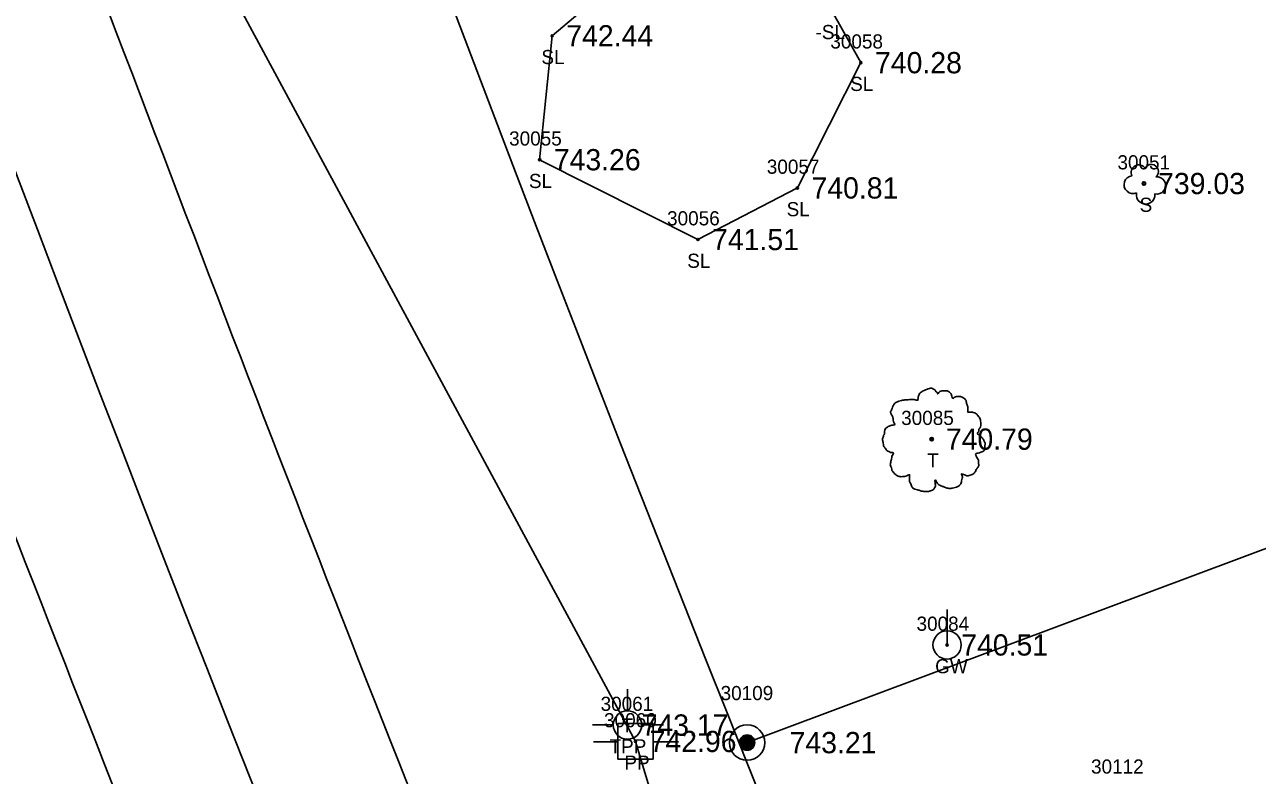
# Model space of a CAD drawing. Extents: x 1375131 to 1378678, y 999028 to 1004053.
# Drawn here: x 1376786.1 to 1376873.2, y 1002668.2 to 1002721.2 of the extents above; entities that cross this region are included whole.
import ezdxf

# ---------------------------------------------------------------- set-up
doc = ezdxf.new("R2010")
doc.units = 0
for name, color, linetype in [('RD_EX_Conc_txCode', 7, 'Continuous'), ('RD_EX_DV_Prop', 7, 'Continuous'), ('RD_EX_DV_Prop_txCode', 7, 'Continuous'), ('RD_EX_DV_PropPin', 7, 'Continuous'), ('RD_EX_Road', 7, 'Continuous'), ('RD_EX_RW', 7, 'Continuous'), ('RD_EX_SU_Elec', 7, 'Continuous'), ('RD_EX_TX_DV_Prop_ELEV', 7, 'Continuous'), ('RD_EX_TX_UT_ELEV', 7, 'Continuous'), ('RD_EX_TX_VEG_ELEV', 7, 'Continuous'), ('RD_EX_UT', 7, 'Continuous'), ('RD_EX_UT_txCode', 7, 'Continuous'), ('RD_EX_VEG', 7, 'Continuous'), ('RD_EX_VEG_txCode', 7, 'Continuous'), ('RD_HC_Cl', 7, 'Continuous'), ('RD_HC_Survey_ELEV', 7, 'Continuous'), ('RD_SMD_Locator', 7, 'Continuous')]:
    doc.layers.add(name, color=color, linetype=linetype)

msp = doc.modelspace()

# ---------------------------------------------------------------- linework, layer by layer
at = {"layer": 'RD_EX_DV_Prop'}
msp.add_line((1376836.626, 1002670.321), (1377239.883, 1002821.263), dxfattribs=at)
at = {"layer": 'RD_EX_DV_PropPin'}
for p, q in [((1376836.825, 1002670.055), (1376836.825, 1002670.961)), ((1376836.85, 1002670.039), (1376836.85, 1002670.977)), ((1376836.875, 1002670.026), (1376836.875, 1002670.99)), ((1376836.9, 1002670.013), (1376836.9, 1002671.003)), ((1376836.925, 1002670.003), (1376836.925, 1002671.013)), ((1376836.95, 1002669.994), (1376836.95, 1002671.022)), ((1376836.975, 1002669.986), (1376836.975, 1002671.03)), ((1376837, 1002669.979), (1376837, 1002671.037)), ((1376837.025, 1002669.974), (1376837.025, 1002671.042)), ((1376837.05, 1002669.97), (1376837.05, 1002671.046)), ((1376837.075, 1002669.967), (1376837.075, 1002671.049)), ((1376837.1, 1002669.965), (1376837.1, 1002671.051)), ((1376837.125, 1002669.965), (1376837.125, 1002671.051)), ((1376837.15, 1002669.965), (1376837.15, 1002671.051)), ((1376837.175, 1002669.967), (1376837.175, 1002671.049)), ((1376837.2, 1002669.97), (1376837.2, 1002671.046)), ((1376837.225, 1002669.974), (1376837.225, 1002671.042)), ((1376837.25, 1002669.979), (1376837.25, 1002671.037)), ((1376837.275, 1002669.986), (1376837.275, 1002671.03)), ((1376837.3, 1002669.994), (1376837.3, 1002671.022)), ((1376837.325, 1002670.003), (1376837.325, 1002671.013)), ((1376837.35, 1002670.013), (1376837.35, 1002671.003)), ((1376837.375, 1002670.026), (1376837.375, 1002670.99)), ((1376837.4, 1002670.039), (1376837.4, 1002670.977)), ((1376837.425, 1002670.055), (1376837.425, 1002670.961)), ((1376836.6, 1002670.368), (1376836.6, 1002670.648)), ((1376836.625, 1002670.295), (1376836.625, 1002670.721)), ((1376836.65, 1002670.244), (1376836.65, 1002670.772)), ((1376836.675, 1002670.203), (1376836.675, 1002670.813)), ((1376836.7, 1002670.169), (1376836.7, 1002670.847)), ((1376836.725, 1002670.14), (1376836.725, 1002670.876)), ((1376836.75, 1002670.115), (1376836.75, 1002670.901)), ((1376836.775, 1002670.092), (1376836.775, 1002670.924)), ((1376836.8, 1002670.073), (1376836.8, 1002670.943)), ((1376837.45, 1002670.073), (1376837.45, 1002670.943)), ((1376837.475, 1002670.092), (1376837.475, 1002670.924)), ((1376837.5, 1002670.115), (1376837.5, 1002670.901)), ((1376837.525, 1002670.14), (1376837.525, 1002670.876)), ((1376837.55, 1002670.169), (1376837.55, 1002670.847)), ((1376837.575, 1002670.203), (1376837.575, 1002670.813)), ((1376837.6, 1002670.244), (1376837.6, 1002670.772)), ((1376837.625, 1002670.295), (1376837.625, 1002670.721)), ((1376837.65, 1002670.368), (1376837.65, 1002670.648))]:
    msp.add_line(p, q, dxfattribs=at)
for radius in [1.25, 0.543]:
    msp.add_circle((1376837.125, 1002670.508), radius, dxfattribs=at)
at = {"layer": 'RD_EX_Road'}
for points in [[(1377013.314, 1002264.907), (1376982.808, 1002315.683), (1376952.468, 1002370.341), (1376923.174, 1002424.32), (1376895.644, 1002480.03), (1376870.11, 1002535.049), (1376846.329, 1002588.864), (1376822.292, 1002645.031), (1376786.564, 1002736.458)], [(1376994.747, 1002253.913), (1376964.909, 1002306.463), (1376934.396, 1002359.987), (1376904.773, 1002415.485), (1376877.271, 1002471.511), (1376851.037, 1002526.893), (1376827.48, 1002581.62), (1376804.191, 1002637.821), (1376768.457, 1002728.838)]]:
    msp.add_spline(points, degree=3, dxfattribs=at)
at = {"layer": 'RD_EX_RW'}
for radius in [2767, 2833]:
    msp.add_arc((1379404.86, 1003700.108), radius, 200.269954, 211.131166, dxfattribs=at)
at = {"layer": 'RD_EX_SU_Elec'}
for p, q in [((1376639.019, 1003023.14), (1376829.238, 1002670.592)), ((1376829.238, 1002670.592), (1376932.6, 1002329.066))]:
    msp.add_line(p, q, dxfattribs=at)
at = {"layer": 'RD_EX_UT'}
for p, q in [((1376851.25, 1002677.405), (1376851.25, 1002679.905)), ((1376828.672, 1002674.285), (1376828.672, 1002672.75)), ((1376830.483, 1002671.847), (1376827.983, 1002671.847)), ((1376827.983, 1002671.847), (1376827.983, 1002669.347)), ((1376830.483, 1002669.347), (1376830.483, 1002671.847)), ((1376826.207, 1002671.758), (1376827.672, 1002671.758)), ((1376829.672, 1002671.758), (1376831.207, 1002671.758)), ((1376826.268, 1002670.565), (1376828.002, 1002670.565)), ((1376830.448, 1002670.565), (1376832.268, 1002670.565)), ((1376827.983, 1002669.347), (1376830.483, 1002669.347))]:
    msp.add_line(p, q, dxfattribs=at)
for centre in [(1376851.25, 1002677.405), (1376828.672, 1002671.75)]:
    msp.add_circle(centre, 1, dxfattribs=at)
at = {"layer": 'RD_EX_VEG'}
msp.add_lwpolyline([(1376842.762, 1002723.226), (1376832.093, 1002727.803), (1376823.348, 1002720.418), (1376822.468, 1002711.668), (1376833.651, 1002706.033), (1376840.672, 1002709.675), (1376845.16, 1002718.521), (1376843.119, 1002722.182)], dxfattribs=at)
for centre, radius in [((1376865.158, 1002709.986), 0.125), ((1376850.164, 1002691.938), 0.125), ((1376850.158, 1002691.929), 0.00005)]:
    msp.add_circle(centre, radius, dxfattribs=at)
for centre, radius, start, end in [((1376864.797, 1002710.76), 0.542, 34.97629, 204.75602), ((1376865.681, 1002710.837), 0.497, 308.76261, 152.04674), ((1376864.376, 1002709.908), 0.628, 96.45179, 294.73401), ((1376866.078, 1002709.846), 0.609, 256.56668, 98.10463), ((1376865.281, 1002709.188), 0.659, 166.88266, 5.75893)]:
    msp.add_arc(centre, radius, start, end, dxfattribs=at)
for points in [[(1376850.23, 1002695.522), (1376850.08, 1002695.534), (1376849.918, 1002695.484), (1376849.793, 1002695.434), (1376849.68, 1002695.397), (1376849.568, 1002695.347), (1376849.418, 1002695.259), (1376849.305, 1002695.159), (1376849.243, 1002695.034), (1376849.218, 1002694.922), (1376849.193, 1002694.784), (1376849.193, 1002694.697), (1376849.13, 1002694.684), (1376849.055, 1002694.697), (1376848.931, 1002694.734), (1376848.806, 1002694.734), (1376848.681, 1002694.734), (1376848.506, 1002694.722), (1376848.331, 1002694.722), (1376848.193, 1002694.697), (1376848.031, 1002694.672), (1376847.844, 1002694.61), (1376847.669, 1002694.547), (1376847.519, 1002694.422), (1376847.394, 1002694.185), (1376847.331, 1002694.01), (1376847.256, 1002693.885), (1376847.331, 1002693.66), (1376847.419, 1002693.485), (1376847.431, 1002693.385), (1376847.469, 1002693.173), (1376847.519, 1002693.06), (1376847.581, 1002692.96), (1376847.544, 1002692.948), (1376847.356, 1002692.923), (1376847.206, 1002692.873), (1376846.994, 1002692.76), (1376846.881, 1002692.648), (1376846.831, 1002692.485), (1376846.819, 1002692.311), (1376846.769, 1002692.211), (1376846.732, 1002692.073), (1376846.719, 1002692.036), (1376846.694, 1002691.873), (1376846.744, 1002691.648), (1376846.757, 1002691.473), (1376846.819, 1002691.361), (1376846.894, 1002691.274), (1376846.981, 1002691.149), (1376847.181, 1002691.036), (1376847.344, 1002690.986), (1376847.444, 1002690.974), (1376847.356, 1002690.724), (1376847.331, 1002690.549), (1376847.269, 1002690.349), (1376847.269, 1002690.311), (1376847.244, 1002690.074), (1376847.319, 1002689.912), (1376847.356, 1002689.724), (1376847.444, 1002689.612), (1376847.581, 1002689.462), (1376847.744, 1002689.349), (1376847.993, 1002689.287), (1376848.193, 1002689.299), (1376848.481, 1002689.387), (1376848.606, 1002689.424), (1376848.593, 1002689.337), (1376848.606, 1002689.149), (1376848.606, 1002688.937), (1376848.681, 1002688.775), (1376848.731, 1002688.637), (1376848.806, 1002688.512), (1376848.968, 1002688.4), (1376849.168, 1002688.362), (1376849.38, 1002688.287), (1376849.605, 1002688.25), (1376849.855, 1002688.237), (1376850.155, 1002688.312), (1376850.292, 1002688.375), (1376850.342, 1002688.462), (1376850.442, 1002688.65), (1376850.417, 1002688.762), (1376850.43, 1002689.062), (1376850.48, 1002688.974), (1376850.567, 1002688.8), (1376850.817, 1002688.65), (1376851.017, 1002688.562), (1376851.255, 1002688.487), (1376851.404, 1002688.45), (1376851.642, 1002688.487), (1376851.829, 1002688.525), (1376852.017, 1002688.587), (1376852.167, 1002688.725), (1376852.254, 1002688.862), (1376852.279, 1002688.999), (1376852.317, 1002689.187), (1376852.342, 1002689.274)], [(1376852.342, 1002689.274), (1376852.304, 1002689.362), (1376852.279, 1002689.487), (1376852.317, 1002689.474), (1376852.404, 1002689.449), (1376852.541, 1002689.387), (1376852.654, 1002689.349), (1376852.816, 1002689.362), (1376852.954, 1002689.412), (1376853.179, 1002689.549), (1376853.316, 1002689.787), (1376853.454, 1002689.987), (1376853.491, 1002690.149), (1376853.466, 1002690.261), (1376853.454, 1002690.511), (1376853.354, 1002690.636), (1376853.329, 1002690.699), (1376853.279, 1002690.899), (1376853.316, 1002690.924), (1376853.454, 1002690.949), (1376853.641, 1002691.011), (1376853.778, 1002691.074), (1376853.891, 1002691.161), (1376853.928, 1002691.274), (1376853.916, 1002691.473), (1376853.941, 1002691.673), (1376853.903, 1002691.748), (1376853.853, 1002691.823), (1376853.816, 1002691.923), (1376853.741, 1002691.998), (1376853.691, 1002692.073), (1376853.641, 1002692.123), (1376853.579, 1002692.198), (1376853.491, 1002692.261), (1376853.416, 1002692.286), (1376853.391, 1002692.361), (1376853.466, 1002692.46), (1376853.491, 1002692.51), (1376853.504, 1002692.623), (1376853.616, 1002692.798), (1376853.641, 1002692.998), (1376853.616, 1002693.21), (1376853.591, 1002693.348), (1376853.516, 1002693.485), (1376853.416, 1002693.61), (1376853.354, 1002693.697), (1376853.266, 1002693.76), (1376853.104, 1002693.822), (1376852.979, 1002693.847), (1376852.804, 1002693.847), (1376852.704, 1002693.872), (1376852.716, 1002693.897), (1376852.716, 1002693.972), (1376852.716, 1002694.11), (1376852.679, 1002694.335), (1376852.604, 1002694.585), (1376852.604, 1002694.597), (1376852.554, 1002694.722), (1376852.442, 1002694.822), (1376852.354, 1002694.872), (1376852.254, 1002694.934), (1376852.129, 1002694.947), (1376851.979, 1002694.947), (1376851.842, 1002694.922), (1376851.742, 1002694.872), (1376851.654, 1002694.809), (1376851.617, 1002694.884), (1376851.567, 1002695.034), (1376851.542, 1002695.109), (1376851.467, 1002695.197), (1376851.355, 1002695.297), (1376851.13, 1002695.359), (1376850.817, 1002695.322), (1376850.667, 1002695.222), (1376850.592, 1002695.134), (1376850.567, 1002695.197), (1376850.467, 1002695.297), (1376850.417, 1002695.384), (1376850.33, 1002695.447), (1376850.255, 1002695.497), (1376850.205, 1002695.522)]]:
    msp.add_spline(points, degree=3, dxfattribs=at)
at = {"layer": 'RD_HC_Cl'}
msp.add_arc((1379404.86, 1003700.108), 2800, 200.269954, 211.131166, dxfattribs=at)
at = {"layer": 'RD_SMD_Locator'}
for centre in [(1376823.348, 1002720.418), (1376845.16, 1002718.521), (1376822.468, 1002711.668), (1376840.672, 1002709.675), (1376865.158, 1002709.986), (1376833.651, 1002706.033), (1376850.164, 1002691.938), (1376851.25, 1002677.405), (1376828.672, 1002671.75), (1376829.238, 1002670.592), (1376837.125, 1002670.508)]:
    msp.add_circle(centre, 0.075, dxfattribs=at)

# ---------------------------------------------------------------- texts
at = {"layer": 'RD_EX_Conc_txCode'}
msp.add_text('30112', height=1, dxfattribs=at).set_placement((1376861.419, 1002668.319))
at = {"layer": 'RD_EX_DV_Prop_txCode'}
msp.add_text('30109', height=1, dxfattribs=at).set_placement((1376835.251, 1002673.508))
at = {"layer": 'RD_EX_TX_DV_Prop_ELEV'}
msp.add_text('743.21', height=1.5, dxfattribs=at).set_placement((1376840.125, 1002669.758))
at = {"layer": 'RD_EX_TX_UT_ELEV'}
for s, p in [('740.51', (1376852.25, 1002676.655)), ('743.17', (1376829.672, 1002671))]:
    msp.add_text(s, height=1.5, dxfattribs=at).set_placement(p)
at = {"layer": 'RD_EX_TX_VEG_ELEV'}
for s, p in [('742.44', (1376824.348, 1002719.668)), ('740.28', (1376846.16, 1002717.771)), ('743.26', (1376823.468, 1002710.918)), ('740.81', (1376841.672, 1002708.925)), ('739.03', (1376866.158, 1002709.236)), ('741.51', (1376834.651, 1002705.283)), ('740.79', (1376851.164, 1002691.188))]:
    msp.add_text(s, height=1.5, dxfattribs=at).set_placement(p)
at = {"layer": 'RD_EX_UT'}
msp.add_text('T', height=1, dxfattribs=at).set_placement((1376828.247, 1002671.226))
at = {"layer": 'RD_EX_UT_txCode'}
for s, p in [('30084', (1376849.093, 1002678.405)), ('GW', (1376850.407, 1002675.405)), ('30061', (1376826.774, 1002672.75)), ('30060', (1376827.018, 1002671.592)), ('TPP', (1376827.404, 1002669.75)), ('PP', (1376828.458, 1002668.592))]:
    msp.add_text(s, height=1, dxfattribs=at).set_placement(p)
at = {"layer": 'RD_EX_VEG_txCode'}
for s, p in [('-SL', (1376841.954, 1002720.182)), ('30058', (1376843.003, 1002719.521)), ('SL', (1376822.592, 1002718.418)), ('SL', (1376844.404, 1002716.521)), ('30055', (1376820.311, 1002712.668)), ('30051', (1376863.284, 1002710.986)), ('30057', (1376838.515, 1002710.675)), ('SL', (1376821.712, 1002709.668)), ('SL', (1376839.916, 1002707.675)), ('S', (1376864.851, 1002707.986)), ('30056', (1376831.47, 1002707.033)), ('SL', (1376832.895, 1002704.033)), ('30085', (1376848.007, 1002692.938)), ('T', (1376849.841, 1002689.938))]:
    msp.add_text(s, height=1, dxfattribs=at).set_placement(p)
at = {"layer": 'RD_HC_Survey_ELEV'}
msp.add_text('742.96', height=1.5, dxfattribs=at).set_placement((1376830.238, 1002669.842))

doc.saveas('drawing.dxf')
